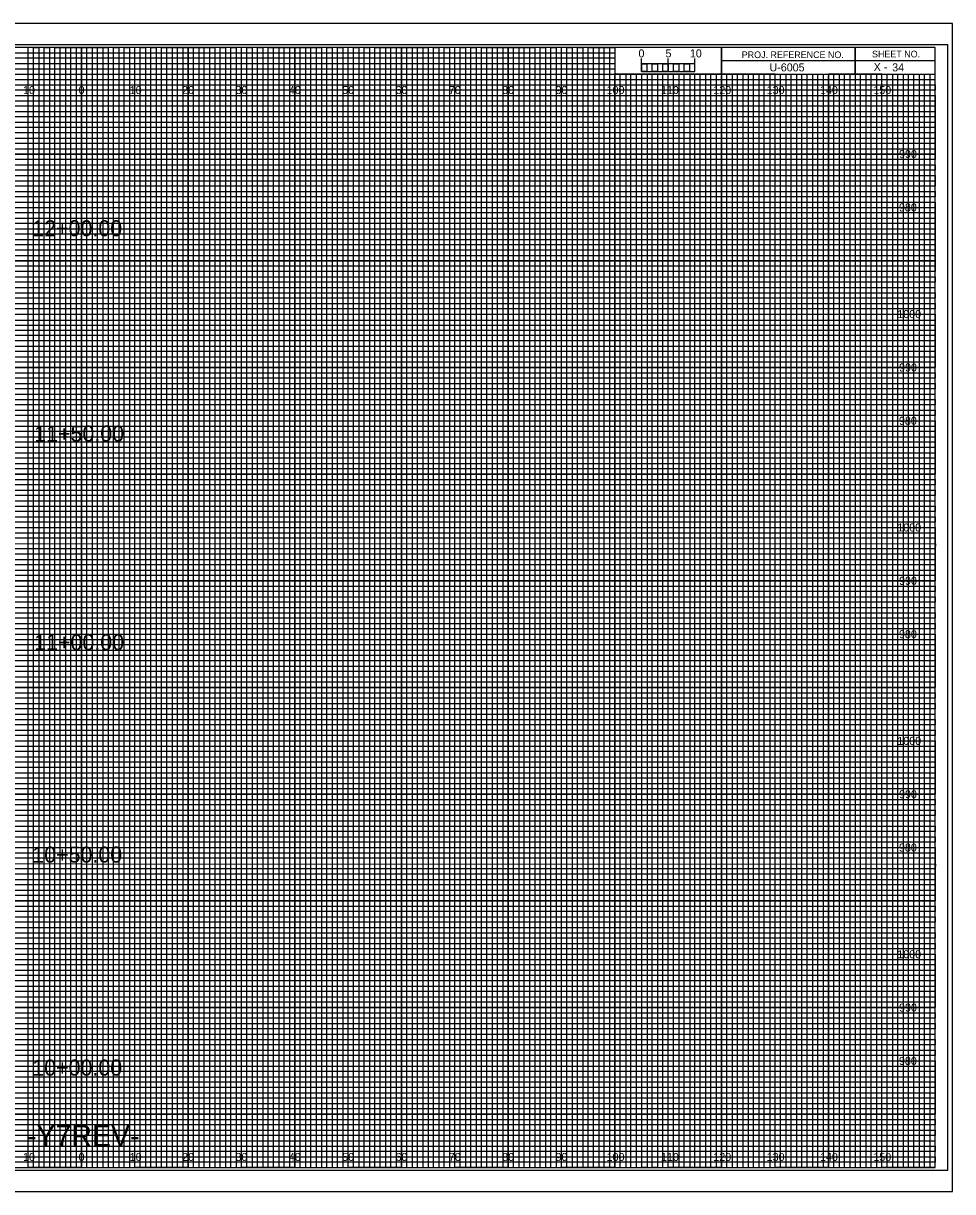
# Model space of a CAD drawing. Extents: x -13 to 323, y -5 to 215.
# Drawn here: x 149.1 to 323.3, y -4.5 to 214.5 of the extents above; entities that cross this region are included whole.
import ezdxf

# ---------------------------------------------------------------- set-up
doc = ezdxf.new("R2010")
doc.units = 0
for name, color, linetype in [('Prop XS Alignment Label', 7, 'Continuous'), ('Prop XS Bar Scale Labels', 7, 'Continuous'), ('Prop XS Elevation Labels', 7, 'Continuous'), ('Prop XS Offset Labels', 7, 'Continuous'), ('Prop XS Project Number', 7, 'Continuous'), ('Prop XS Sheet Number', 7, 'Continuous'), ('Prop XS Station Labels', 7, 'Continuous'), ('Sheet Cross Section CELL', 7, 'Continuous'), ('Sheet Cross Section Grid Major CELL', 7, 'Continuous'), ('Sheet Cross Section Grid Middle CELL', 7, 'Continuous'), ('Sheet Cross Section Grid Minor 1 CELL', 7, 'Continuous'), ('Sheet Cross Section Grid Minor 2 CELL', 7, 'Continuous'), ('Sheet Cross Section Scale CELL', 7, 'Continuous'), ('Sheet Cutting Line CELL', 7, 'Continuous'), ('Sheet DOT Grid CELL', 7, 'Continuous'), ('Sheet Plot Border Inside CELL', 7, 'Continuous'), ('Sheet Plot Border Outside CELL', 7, 'Continuous')]:
    doc.layers.add(name, color=color, linetype=linetype)

msp = doc.modelspace()

# ---------------------------------------------------------------- linework, layer by layer
at = {"layer": 'Sheet Cross Section CELL'}
for p, q in [((305, 210), (305, 205)), ((305, 205), (305, 210)), ((280, 207.5), (280, 205)), ((320, 207.49), (280, 207.49)), ((280, 205), (320, 205))]:
    msp.add_line(p, q, dxfattribs=at)
for points in [[(320, 210), (0, 210), (0, 0), (320, 0)], [(280, 210), (260, 210), (260, 205.03), (280, 205.03)], [(320, 210), (280, 210), (280, 205), (320, 205)]]:
    msp.add_lwpolyline(points, close=True, dxfattribs=at)
at = {"layer": 'Sheet Cross Section Grid Major CELL'}
for p, q in [((150, 210), (140, 210)), ((150, 0), (150, 210)), ((170, 210), (160, 210)), ((160, 210), (160, 0)), ((170, 0), (170, 210)), ((190, 210), (180, 210)), ((180, 210), (180, 0)), ((190, 0), (190, 210)), ((210, 210), (200, 210)), ((200, 210), (200, 0)), ((210, 0), (210, 210)), ((230, 210), (220, 210)), ((220, 210), (220, 0)), ((230, 0), (230, 210)), ((250, 210), (240, 210)), ((240, 210), (240, 0)), ((250, 0), (250, 210)), ((260, 210), (260, 0)), ((270, 0), (270, 205)), ((290, 205), (280, 205)), ((280, 205), (280, 0)), ((290, 0), (290, 205)), ((310, 205), (300, 205)), ((300, 205), (300, 0)), ((310, 0), (310, 205)), ((160, 0), (150, 0)), ((180, 0), (170, 0)), ((200, 0), (190, 0)), ((220, 0), (210, 0)), ((240, 0), (230, 0)), ((260, 0), (250, 0)), ((280, 0), (270, 0)), ((300, 0), (290, 0)), ((320, 0), (310, 0)), ((320, 0), (320, 0))]:
    msp.add_line(p, q, dxfattribs=at)
for points in [[(0, 200), (320, 200), (320, 190), (0, 190)], [(0, 180), (320, 180), (320, 170), (0, 170)], [(0, 160), (320, 160), (320, 150), (0, 150)], [(0, 140), (320, 140), (320, 130), (0, 130)], [(0, 120), (320, 120), (320, 110), (0, 110)], [(0, 100), (320, 100), (320, 90), (0, 90)], [(0, 80), (320, 80), (320, 70), (0, 70)], [(0, 60), (320, 60), (320, 50), (0, 50)], [(0, 40), (320, 40), (320, 30), (0, 30)], [(0, 20), (320, 20), (320, 10), (0, 10)]]:
    msp.add_lwpolyline(points, dxfattribs=at)
at = {"layer": 'Sheet Cross Section Grid Middle CELL'}
for points in [[(145, 0), (155, 0), (155, 210), (165, 210), (165, 0), (175, 0), (175, 210), (185, 210), (185, 0), (195, 0), (195, 210), (205, 210), (205, 0), (215, 0), (215, 210), (225, 210), (225, 0), (235, 0), (235, 210), (245, 210), (245, 0), (255, 0), (255, 210), (259.93, 210), (260, 210), (260, 205), (264.99, 205), (264.99, 0), (275, 0), (275, 205), (285, 205), (285, 0), (295, 0), (295, 205), (305, 205), (305, 0), (315, 0), (315, 205)], [(0, 205), (275, 205)], [(0, 185), (320, 185), (320, 195), (0, 195)], [(0, 165), (320, 165), (320, 175), (0, 175)], [(0, 145), (320, 145), (320, 155), (0, 155)], [(0, 125), (320, 125), (320, 135), (0, 135)], [(0, 105), (320, 105), (320, 115), (0, 115)], [(0, 85), (320, 85), (320, 95), (0, 95)], [(0, 65), (320, 65), (320, 75), (0, 75)], [(0, 45), (320, 45), (320, 55), (0, 55)], [(0, 25), (320, 25), (320, 35), (0, 35)], [(0, 5), (320, 5), (320, 15), (0, 15)]]:
    msp.add_lwpolyline(points, dxfattribs=at)
at = {"layer": 'Sheet Cross Section Grid Minor 1 CELL'}
for p, q in [((0, 209), (260, 209)), ((260, 209), (260, 207.98)), ((260, 207.98), (0, 207.98)), ((0, 207), (260, 207)), ((260, 205.89), (0, 205.89)), ((260, 207), (260, 205.89)), ((0, 204), (320, 204))]:
    msp.add_line(p, q, dxfattribs=at)
for points in [[(0, 203), (270, 203), (320, 203), (320, 202), (0, 202)], [(0, 201), (320, 201), (320, 199), (0, 199)], [(0, 198), (320, 198), (320, 197), (0, 196.98)], [(0, 196), (320, 196), (320, 194), (0, 194)], [(0, 193), (320, 193), (320, 192), (0, 192)], [(0, 191), (320, 191), (320, 189), (0, 189)], [(0, 188), (320, 188), (320, 187), (0, 187)], [(0, 186), (320, 186), (320, 184), (0, 184)], [(0, 183), (320, 183), (320, 182), (0, 182)], [(0, 181), (320, 181), (320, 179), (0, 179)], [(0, 178), (320, 178), (320, 177), (0, 177)], [(0, 176), (320, 176), (320, 173.95), (320, 173), (320, 172), (0, 172)], [(0, 174), (320, 174), (320, 173), (0, 173)], [(0, 171), (320, 171), (320, 169), (0, 169.03)], [(0, 169.03), (320, 169), (320, 168), (0, 168)], [(0, 167), (320, 167), (320, 166), (0, 166)], [(0, 164), (320, 164), (320, 163), (0, 163)], [(0, 162), (320, 162), (320, 161), (0, 161)], [(-0.07, 158.89), (320, 158.89), (320, 157.88), (-0.07, 157.88)], [(0, 157), (320, 157), (320, 156), (0, 156)], [(0, 154), (320, 154), (320, 153), (0, 153)], [(0, 152), (320, 152), (320, 151), (0, 151)], [(0, 149), (320, 149), (320, 148), (0, 148)], [(0, 147), (320, 147), (320, 146), (0, 146)], [(0, 144), (320, 144), (320, 143), (0, 143)], [(0, 142), (320, 142), (320, 141), (0, 141)], [(0, 139), (320, 139), (319.99, 137.98), (0, 138)], [(0, 137), (320, 137), (320, 136), (0, 136)], [(0, 134), (320, 134), (320, 133), (0, 133)], [(0, 132), (320, 132), (320, 131), (0, 131)], [(0, 129), (320, 129), (320, 128), (0, 128)], [(0, 127), (320, 127), (320, 126), (0, 126)], [(0, 124), (320, 124), (320, 123), (0, 123)], [(0, 122), (320, 122), (320, 121), (0, 121)], [(0, 119), (320, 119), (320, 118), (0, 118)], [(0, 116.99), (320.07, 116.91), (320, 116), (0, 116)], [(0, 114), (320, 114), (320, 113), (0, 113)], [(0, 112), (320, 112), (320, 111), (0, 111)], [(0, 109), (320, 109), (320, 108), (0, 108)], [(0, 107), (320, 107), (320, 106), (0, 106)], [(0, 104), (320, 104), (320, 103), (0, 103)], [(0, 102), (320, 102), (320, 101), (0, 101)], [(0, 99), (320, 99), (320, 98), (0, 98)], [(0, 97), (320, 97), (320, 96), (0, 96)], [(0, 94), (320, 94), (320, 93), (0, 93)], [(0, 92), (320, 92), (320, 91), (0, 91)], [(0, 89), (320, 89), (320, 88), (0, 88)], [(0, 87), (320, 87), (320, 86), (0, 86)], [(0, 84), (320, 84), (320, 83), (0, 83)], [(0, 82), (320, 82), (320, 81), (0, 81)], [(0, 79), (320, 79), (319.99, 77.98), (0, 78)], [(0, 77), (320, 77), (320, 76), (0, 76)], [(0, 74), (320, 74), (320, 73), (0, 73)], [(0, 72), (320, 72), (320, 71), (0, 71)], [(0, 69), (320, 69), (320, 68), (0, 68)], [(0, 67), (320, 67), (320, 66), (0, 66)], [(0, 64), (320, 64), (320, 63), (0, 63)], [(0, 62), (320, 62), (320, 61), (0, 61)], [(0, 59), (320, 59), (320, 58), (0, 58)], [(0, 56.99), (320.07, 56.91), (320, 56), (0, 56)], [(0, 54), (320, 54), (320, 53), (0, 53)], [(0, 52), (320, 52), (320, 51), (0, 51)], [(0, 49), (320, 49), (320, 48), (0, 48)], [(0, 47), (320, 47), (320, 46), (0, 46)], [(0, 44), (320, 44), (320, 43), (0, 43)], [(0, 42), (320, 42), (320, 41), (0, 41)], [(0, 39), (320, 39), (320, 38), (0, 38)], [(0, 37), (320, 37), (320, 36), (0, 36)], [(0, 34), (320, 34), (320, 33), (0, 33)], [(0, 32), (320, 32), (320, 31), (0, 31)], [(0, 29), (320, 29), (320, 28), (0, 28)], [(0, 27), (320, 27), (320, 26), (0, 26)], [(0, 24), (320, 24), (320, 23), (0, 23)], [(0, 22), (320, 22), (320, 21), (0, 21)], [(0, 19), (320, 19), (320, 18), (0, 18)], [(0, 17), (320, 17), (320, 16), (0, 16)], [(0, 14), (320, 14), (320, 13), (0, 13)], [(0, 12), (320, 12), (320, 11), (0, 11)], [(0, 9), (320, 9), (320, 8), (0, 8)], [(0, 7), (320, 7), (320, 6), (0, 6)], [(0, 4), (320, 4), (320, 3), (0, 3)], [(0, 2), (320, 2), (320, 1), (0, 1)]]:
    msp.add_lwpolyline(points, dxfattribs=at)
at = {"layer": 'Sheet Cross Section Grid Minor 2 CELL'}
for p, q in [((267, 205), (266.01, 205)), ((266.01, 205), (266.01, 0)), ((267, 0), (267, 205)), ((269, 205), (268, 205)), ((268, 205), (268, 0)), ((269, 0), (269, 205)), ((266.01, 0), (265, 0)), ((268, 0), (267, 0))]:
    msp.add_line(p, q, dxfattribs=at)
for points in [[(150, 0), (151, 0), (151, 210), (152, 210), (152, 0)], [(152, 0), (153, 0), (153, 210), (154, 210), (154, 0)], [(155, 0), (156, 0), (156, 210), (157, 210), (157, 0)], [(157, 0), (158, 0), (158, 210), (159, 210), (159, 0)], [(160, 0), (161, 0), (161, 210), (162, 210), (162, 0)], [(162, 0), (163, 0), (163, 210), (164, 210), (164, 0)], [(165, 0), (166, 0), (166, 210), (167, 210), (167, 0)], [(167, 0), (168, 0), (168, 210), (169, 210), (169, 0)], [(170, 0), (171, 0), (171, 210), (172, 210), (172, 0)], [(172, 0), (173, 0), (173, 210), (174, 210), (174, 0)], [(175, 0), (176, 0), (176, 210), (177, 210), (177, 0)], [(177, 0), (178, 0), (178, 210), (179, 210), (179, 0)], [(180, 0), (181, 0), (181, 210), (182, 210), (182, 0)], [(182, 0), (183, 0), (183, 210), (184, 210), (184, 0)], [(185, 0), (186, 0), (186, 210), (187, 210), (187, 0)], [(187, 0), (188, 0), (188, 210), (189, 210), (189, 0)], [(190, 0), (191, 0), (191, 210), (192, 210), (192, 0)], [(192, 0), (193, 0), (193, 210), (194, 210), (194, 0)], [(195, 0), (196, 0), (196, 210), (197, 210), (197, 0)], [(197, 0), (198, 0), (198, 210), (199, 210), (199, 0)], [(200, 0), (201, 0), (201, 210), (202, 210), (202, 0)], [(202, 0), (203, 0), (203, 210), (204, 210), (204, 0)], [(205, 0), (206, 0), (206, 210), (207, 210), (207, 0)], [(207, 0), (208, 0), (208, 210), (209, 210), (209, 0)], [(210, 0), (211, 0), (211, 210), (212, 210), (212, 0)], [(212, 0), (213, 0), (213, 210), (214, 210), (214, 0)], [(215, 0), (216, 0), (216, 210), (217, 210), (217, 0)], [(217, 0), (218, 0), (218, 210), (219, 210), (219, 0)], [(220, 0), (221, 0), (221, 210), (222, 210), (222, 0)], [(222, 0), (223, 0), (223, 210), (224, 210), (224, 0)], [(225, 0), (226, 0), (226, 210), (227, 210), (227, 0)], [(227, 0), (228, 0), (228, 210), (229, 210), (229, 0)], [(230, 0), (231, 0), (231, 210), (232, 210), (232, 0)], [(232, 0), (233, 0), (233, 210), (234, 210), (234, 0)], [(235, 0), (236, 0), (236, 210), (237, 210), (237, 0)], [(237, 0), (238, 0), (238, 210), (239, 210), (239, 0)], [(240, 0), (241, 0), (241, 210), (242, 210), (242, 0)], [(242, 0), (243, 0), (243, 210), (244, 210), (244, 0)], [(245, 0), (246, 0), (246, 210), (247, 210), (247, 0)], [(247, 0), (248, 0), (248, 210), (249, 210), (249, 0)], [(250, 0), (251, 0), (251, 210), (252, 210), (252, 0)], [(252, 0), (253, 0), (253, 210), (254, 210), (254, 0)], [(255, 0), (256, 0), (256, 210), (257, 210), (257, 0)], [(257, 0), (258, 0), (258, 210), (259, 210), (259, 0)], [(260, 0), (261, 0), (261, 205), (262.02, 205), (262.02, 0)], [(262, 0), (263, 0), (263, 205), (263.99, 205), (263.99, 0)], [(270, 0), (270.98, 0), (270.98, 205), (272, 205), (272, 0)], [(272, 0), (273, 0), (273, 205), (274.05, 205), (274.05, 0)], [(275, 0), (276, 0), (276, 205), (277, 205), (277, 0)], [(277, 0), (278, 0), (278, 205), (279, 205), (279, 0)], [(280, 0), (281, 0), (281, 205), (282, 205), (282, 0)], [(282, 0), (283, 0), (283, 205), (284, 205), (284, 0)], [(285, 0), (286, 0), (286, 205), (287, 205), (287, 0)], [(287, 0), (288, 0), (288, 205), (289, 205), (289, 0)], [(290, 0), (291, 0), (291, 205), (292, 205), (292, 0)], [(292, 0), (293, 0), (293, 205), (294, 205), (294, 0)], [(295, 0), (296, 0), (296, 205), (297, 205), (297, 0)], [(297, 0), (298, 0), (298, 205), (299, 205), (299, 0)], [(300, 0), (301, 0), (301, 205), (302, 205), (302, 0)], [(302, 0), (303, 0), (303, 205), (304, 205), (304, 0)], [(305, 0), (306, 0), (306, 205), (307, 205), (307, 0)], [(307, 0), (308, 0), (308, 205), (309, 205), (309, 0)], [(310, 0), (311, 0), (311, 205), (312, 205), (312, 0)], [(312, 0), (313, 0), (313, 205), (314, 205), (314, 0)], [(315, 0), (316, 0), (316, 205), (317, 205), (317, 0)], [(317, 0), (318, 0), (318, 205), (319, 205), (319, 0)]]:
    msp.add_lwpolyline(points, dxfattribs=at)
at = {"layer": 'Sheet Cross Section Scale CELL'}
for p, q in [((265, 205.49), (265, 207.9)), ((265, 206.9), (265, 207.9)), ((270, 205.49), (270, 207.9)), ((275, 205.49), (275, 207.9)), ((275, 206.9), (275, 207.9))]:
    msp.add_line(p, q, dxfattribs=at)
for points in [[(275, 206.9), (265, 206.9), (265, 205.49), (275, 205.49)], [(265, 206.9), (266, 206.9), (266, 205.49), (265, 205.49)], [(267, 206.9), (268, 206.9), (268, 205.49), (267, 205.49)], [(269, 206.9), (270, 206.9), (270, 205.49), (269, 205.49)], [(271, 206.9), (272, 206.9), (272, 205.49), (271, 205.49)], [(273, 206.9), (274, 206.9), (274, 205.49), (273, 205.49)]]:
    msp.add_lwpolyline(points, close=True, dxfattribs=at)
at = {"layer": 'Sheet Cutting Line CELL'}
for p, q in [((323.3, 214.5), (-13.4, 214.5)), ((-13.4, -4.5), (323.3, -4.5))]:
    msp.add_line(p, q, dxfattribs=at)
at = {"layer": 'Sheet DOT Grid CELL'}
for p, q in [((150, 0), (150, 210)), ((160, 0), (160, 210)), ((170, 0), (170, 210)), ((180, 0), (180, 210)), ((190, 0), (190, 210)), ((200, 0), (200, 210)), ((210, 0), (210, 210)), ((220, 0), (220, 210)), ((230, 0), (230, 210)), ((240, 0), (240, 210)), ((250, 0), (250, 210)), ((260, 0), (260, 204.69)), ((270, 0), (270, 204.69)), ((280, 0), (280, 204.69)), ((290, 0), (290, 204.69)), ((300, 0), (300, 204.69)), ((310, 0), (310, 204.69)), ((0, 200), (320, 200)), ((0, 190), (320, 190)), ((0, 180), (320, 180)), ((0, 170), (320, 170)), ((0, 160), (320, 160)), ((0, 150), (320, 150)), ((0, 140), (320, 140)), ((0, 130), (320, 130)), ((0, 120), (320, 120)), ((0, 110), (320, 110)), ((0, 100), (320, 100)), ((0, 90), (320, 90)), ((0, 80), (320, 80)), ((0, 70), (320, 70)), ((0, 60), (320, 60)), ((0, 50), (320, 50)), ((0, 40), (320, 40)), ((0, 30), (320, 30)), ((0, 20), (320, 20)), ((0, 10), (320, 10))]:
    msp.add_line(p, q, dxfattribs=at)
at = {"layer": 'Sheet Plot Border Inside CELL'}
msp.add_lwpolyline([(-10.8, -0.5), (322.4, -0.5), (322.4, 210.5), (-10.8, 210.5)], close=True, dxfattribs=at)
at = {"layer": 'Sheet Plot Border Outside CELL'}
msp.add_lwpolyline([(-13.4, -4.5), (323.3, -4.5), (323.3, 214.5), (-13.4, 214.5)], close=True, dxfattribs=at)

# ---------------------------------------------------------------- texts
at = {"layer": 'Prop XS Alignment Label'}
msp.add_text('-Y7REV-', height=4, dxfattribs=at).set_placement((149.77, 4))
at = {"layer": 'Prop XS Bar Scale Labels'}
for s, p in [('5', (269.47, 208.12)), ('10', (274.04, 208.12))]:
    msp.add_text(s, height=1.5, dxfattribs=at).set_placement(p)
at = {"layer": 'Prop XS Elevation Labels'}
for s, p in [('990', (313.26, 189.25)), ('980', (313.24, 179.25)), ('1000', (312.92, 159.25)), ('990', (313.26, 149.25)), ('980', (313.24, 139.25)), ('1000', (312.92, 119.25)), ('990', (313.26, 109.25)), ('980', (313.24, 99.25)), ('1000', (312.92, 79.25)), ('990', (313.26, 69.25)), ('980', (313.24, 59.25)), ('1000', (312.92, 39.25)), ('990', (313.26, 29.25)), ('980', (313.24, 19.25))]:
    msp.add_text(s, height=1.5, dxfattribs=at).set_placement(p)
at = {"layer": 'Prop XS Offset Labels'}
for s, p in [('10', (149.04, 201.25)), ('0', (159.45, 201.25)), ('0', (159.45, 201.25)), ('10', (169.04, 201.25)), ('20', (178.86, 201.25)), ('30', (188.86, 201.25)), ('40', (198.86, 201.25)), ('50', (208.86, 201.25)), ('60', (218.86, 201.25)), ('70', (228.86, 201.25)), ('80', (238.86, 201.25)), ('90', (248.86, 201.25)), ('100', (258.44, 201.25)), ('110', (268.62, 201.25)), ('120', (278.44, 201.25)), ('130', (288.44, 201.25)), ('140', (298.44, 201.25)), ('150', (308.44, 201.25)), ('10', (149.04, 1.25)), ('0', (159.45, 1.25)), ('0', (159.45, 1.25)), ('10', (169.04, 1.25)), ('20', (178.86, 1.25)), ('30', (188.86, 1.25)), ('40', (198.86, 1.25)), ('50', (208.86, 1.25)), ('60', (218.86, 1.25)), ('70', (228.86, 1.25)), ('80', (238.86, 1.25)), ('90', (248.86, 1.25)), ('100', (258.44, 1.25)), ('110', (268.62, 1.25)), ('120', (278.44, 1.25)), ('130', (288.44, 1.25)), ('140', (298.44, 1.25)), ('150', (308.44, 1.25))]:
    msp.add_text(s, height=1.5, dxfattribs=at).set_placement(p)
at = {"layer": 'Prop XS Project Number'}
msp.add_text('U-6005', height=1.5, dxfattribs=at).set_placement((288.97, 205.5))
at = {"layer": 'Prop XS Sheet Number'}
msp.add_text('34', height=1.5, dxfattribs=at).set_placement((311.97, 205.5))
at = {"layer": 'Prop XS Station Labels'}
for s, p in [('12+00.00', (150.77, 174.59)), ('11+50.00', (151.13, 136.1)), ('11+00.00', (151.13, 96.99)), ('10+50.00', (150.77, 57.18)), ('10+00.00', (150.77, 17.25))]:
    msp.add_text(s, height=3, dxfattribs=at).set_placement(p)
at = {"layer": 'Sheet Cross Section CELL'}
for s, height, p in [('PROJ. REFERENCE NO.', 1.25, (283.77, 207.99)), ('SHEET NO.', 1.25, (308.19, 208.12)), ('X -    ', 1.5, (308.5, 205.58))]:
    msp.add_text(s, height=height, dxfattribs=at).set_placement(p)
at = {"layer": 'Sheet Cross Section Scale CELL'}
msp.add_text('0', height=1.5, dxfattribs=at).set_placement((264.41, 208.12))

doc.saveas('drawing.dxf')
